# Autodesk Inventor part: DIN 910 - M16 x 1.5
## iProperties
Created: 2009-02
Part Number: DIN 910 - M16 x 1.5
Material: Steel, Mild
Description: Screw Plug
Document SubType Name: Modeling
Standard: DIN 910
Designer: 904Chiaki
Standards Organization: DIN
Language: en-US
Size Designation: M16 x 1.5
Categories: <MemberInstance><Categories><Category DisplayName="Other Parts" InternalName="5aa15e00-363f-49f2-933f-16f664388e3f" Mnemonic="OTHER"><Category DisplayName="Plug
Density: 7.86 g/cm^3
Mass: 37.5662 g
Surface Area: 18.509 cm^2
Volume: 4.77942 cm^3
IsCustomPart: 0
Author: 904Chiaki
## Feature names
1. Body [Revolution]
2. Head [Extrusion]
3. Fillet1
4. Chamfer1 [Revolution]
5. Chamfer2
